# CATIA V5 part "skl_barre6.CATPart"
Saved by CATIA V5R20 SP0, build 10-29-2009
Part number: skl_barre6
Publications: "Barre_6", "Axe_Pivot_b6b5", "Axe_Pivot_b6b3"
Bounding box of the stored display mesh (mm): x -159.748 to 234.923, y -381.857 to 0, z 0 to 20
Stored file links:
  C:\Users\Matthieu\Desktop\IFMA\Cours 2A\Thinkmotion\skl_barre6.CATPart
  C:\Users\Matthieu\Desktop\IFMA\Cours 2A\Thinkmotion\skl_IAO_bis.CATProduct
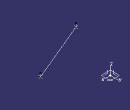
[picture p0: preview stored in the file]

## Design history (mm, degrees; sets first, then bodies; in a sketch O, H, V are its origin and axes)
AxisSystem1: origin (0, 0, 0), X (1, 0, 0), Y (0, 1, 0), Z (0, 0, 1)
Set1
  Point1 "Point.D": linked copy from another document
  Point2 "Point.F": linked copy from another document
  Plane1 "Plan_Ref": linked copy from another document
Body1 (main body)
  Line1 "Barre_6": type PtPt, FirstPoint Point1, SecondPoint Point2
  Line2 "Axe_Pivot_b6b5": type Normal, RefPoint Point2, RefSkin Plane1, Start 0, End 20
  Line3 "Axe_Pivot_b6b3": type Normal, RefPoint Point1, RefSkin Plane1, Start 0, End 20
